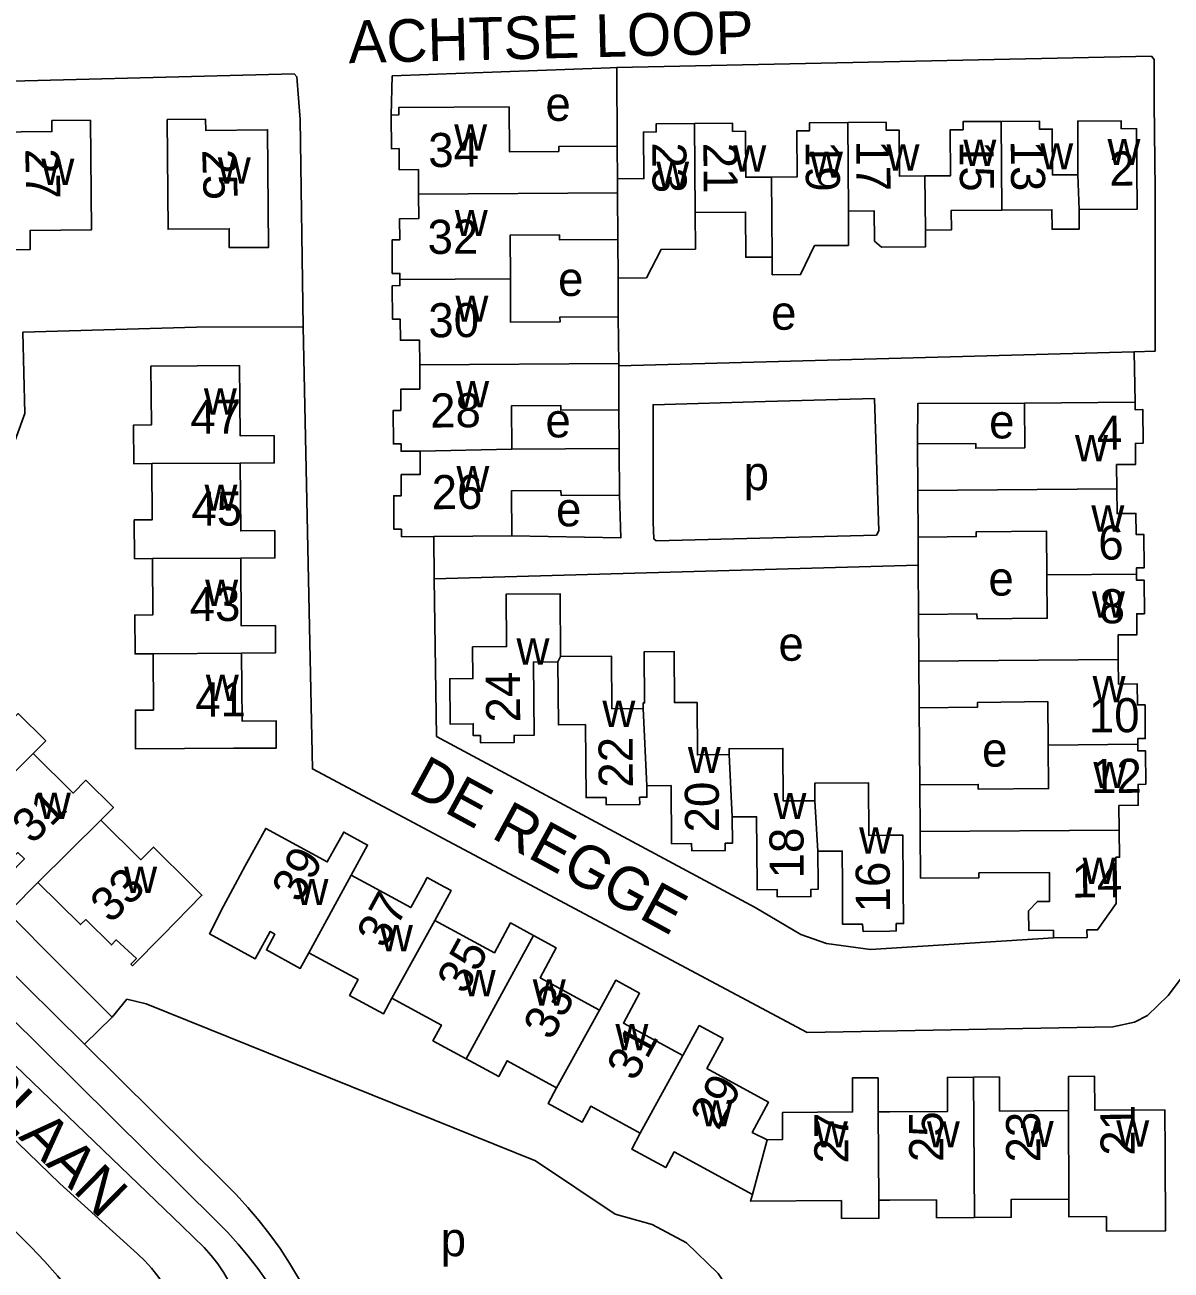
# Model space of a CAD drawing. Extents: x 156721 to 158827, y 386657 to 388950.
# Drawn here: x 157898.5 to 158033, y 387454.8 to 387600.8 of the extents above; entities that cross this region are included whole.
import ezdxf

# ---------------------------------------------------------------- set-up
doc = ezdxf.new("R2010")
doc.units = 0
for name, color, linetype in [('BLT_Basislijn', 7, 'Continuous'), ('BLT_Bebouwing', 7, 'Continuous'), ('BLT_Centroide', 7, 'Continuous'), ('BLT_Huisnummer', 7, 'Continuous'), ('BLT_Huisnummer_ tussenligend', 7, 'Continuous'), ('BLT_Onderverdeling_panden', 7, 'Continuous'), ('BLT_Straatnaam', 7, 'Continuous')]:
    doc.layers.add(name, color=color, linetype=linetype)

msp = doc.modelspace()

# ---------------------------------------------------------------- linework, layer by layer
at = {"layer": 'BLT_Basislijn'}
for p, q in [((157968.01, 387586.61), (157967.99, 387595.81)), ((157968.12, 387571.13), (157968.15, 387566.6)), ((157968.19, 387560.85), (158028.67, 387562.48)), ((158028.67, 387562.48), (158028.8, 387556.58)), ((157968.22, 387555.68), (157968.25, 387551.13)), ((157946.55, 387535.85), (157946.51, 387540.82)), ((158003.32, 387540.75), (158003.34, 387537.44)), ((157905.51, 387481.25), (157848.93, 387537.22)), ((158003.34, 387537.44), (158003.39, 387531.68)), ((158003.54, 387511.67), (158003.47, 387520.73)), ((157846.26, 387519.37), (157902.62, 387464.91)), ((157921.86, 387465.08), (157905.51, 387481.25)), ((157902.62, 387464.91), (157911.72, 387456.67)), ((157919.56, 387457.42), (157916.95, 387459.93))]:
    msp.add_line(p, q, dxfattribs=at)
for points in [[(157967.99, 387595.81), (158030.71, 387597.15), (158031.03, 387596.78), (158031.04, 387591.6), (158031.16, 387581.55), (158031.13, 387562.54), (158028.67, 387562.48)], [(157941.5, 387590.24), (157941.63, 387594.85), (157967.19, 387595.79), (157967.99, 387595.81)], [(157867.9, 387593.86), (157879.95, 387594.35), (157887.95, 387594.01), (157930.12, 387595.07), (157930.44, 387594.75), (157930.8, 387589.72), (157931.18, 387565.39)], [(157931.18, 387565.39), (157918.65, 387565.36), (157898.28, 387564.78), (157898.5, 387555.26), (157894.88, 387545.33), (157882.58, 387532.55), (157875.52, 387525.38), (157871.76, 387521.45)], [(158050, 387530.58), (158045.98, 387530.47), (158041.99, 387530.39), (158042.21, 387499.63), (158032.66, 387486.97), (158030.23, 387484.62), (158028.73, 387483.83), (158026.16, 387483.3), (157990.32, 387482.65), (157932.26, 387513.56), (157931.18, 387565.39)], [(157985.42, 387556.64), (157998.2, 387556.99), (157998.71, 387541.47), (157998.43, 387540.99), (157972.59, 387540.29), (157972.32, 387540.53), (157972.24, 387542.48), (157972.22, 387556.27), (157985.42, 387556.64)], [(158015.81, 387556.47), (158003.3, 387556.43), (158003.24, 387551.69)], [(157955.65, 387540.89), (157968.46, 387540.67), (157968.29, 387545.67)], [(158003.34, 387537.44), (157946.55, 387535.85)], [(157946.55, 387535.85), (157946.82, 387517.36), (157984.19, 387497.31), (157989.55, 387494.14), (157992.58, 387493.09), (157997.76, 387492.37), (158019.21, 387493.73)], [(157921.02, 387460.48), (157855.63, 387525.18), (157851.43, 387523.47)], [(157916.95, 387459.93), (157891.13, 387484.75), (157851.43, 387523.47)], [(157908.77, 387484.42), (157871.76, 387521.45)], [(157992.06, 387443.43), (157983.32, 387449.11), (157979.87, 387454.37), (157976.14, 387457.96), (157972.11, 387460.13), (157967.78, 387461.33), (157958.43, 387467.56), (157912.75, 387485.99), (157910.48, 387486.54), (157908.77, 387484.42)], [(157905.51, 387481.25), (157908.77, 387484.42)], [(157921.86, 387465.08), (157923.3, 387463.62), (157924.68, 387462.12), (157926, 387460.55), (157927.25, 387458.94), (157928.45, 387457.28), (157929.57, 387455.58), (157930.63, 387453.83), (157931.62, 387452.04), (157932.54, 387450.22), (157933.39, 387448.36), (157934.17, 387446.47), (157934.87, 387444.55), (157935.49, 387442.6), (157936.04, 387440.63), (157936.18, 387440.04)], [(157894.22, 387462.09), (157895.95, 387460.61), (157897.64, 387459.06), (157899.26, 387457.46), (157900.83, 387455.8), (157902.34, 387454.09), (157903.79, 387452.33), (157905.18, 387450.51), (157906.5, 387448.65), (157907.76, 387446.75), (157908.95, 387444.8), (157910.07, 387442.81), (157911.12, 387440.78), (157912.1, 387438.71)], [(157921.02, 387460.48), (157922.32, 387459.18), (157923.55, 387457.82), (157924.73, 387456.41), (157925.84, 387454.96), (157926.89, 387453.45), (157927.87, 387451.91), (157928.78, 387450.32), (157929.63, 387448.69), (157930.4, 387447.02), (157931.1, 387445.33), (157931.72, 387443.6), (157932.27, 387441.85), (157932.74, 387440.08), (157933.13, 387438.29), (157933.44, 387436.49), (157933.51, 387436.03)], [(157919.56, 387457.42), (157920.39, 387456.48), (157921.16, 387455.48), (157921.87, 387454.44), (157922.5, 387453.36), (157923.07, 387452.23), (157923.56, 387451.08), (157923.98, 387449.89), (157924.33, 387448.68), (157924.59, 387447.45), (157924.78, 387446.21), (157924.87, 387445.26)], [(157911.72, 387456.67), (157912.58, 387455.85), (157913.38, 387454.97), (157914.13, 387454.05), (157914.81, 387453.07), (157915.42, 387452.05), (157915.97, 387451), (157916.44, 387449.9), (157916.83, 387448.78), (157917.15, 387447.64), (157917.4, 387446.48), (157917.56, 387445.3), (157917.64, 387444.25)]]:
    msp.add_lwpolyline(points, dxfattribs=at)
at = {"layer": 'BLT_Bebouwing'}
for p, q in [((157968.01, 387586.61), (157968.04, 387582.77)), ((157968.15, 387566.6), (157968.19, 387561.11)), ((157968.19, 387561.11), (157968.19, 387560.85)), ((157968.19, 387560.85), (157968.22, 387555.68)), ((158015.81, 387556.47), (158028.8, 387556.58)), ((157955.65, 387551.05), (157968.25, 387551.13)), ((157968.25, 387551.13), (157968.29, 387545.67)), ((158003.28, 387546.22), (158003.24, 387551.69)), ((158003.32, 387540.75), (158003.28, 387546.22)), ((158003.43, 387526.21), (158003.39, 387531.68)), ((158003.47, 387520.73), (158003.43, 387526.21)), ((158003.58, 387506.2), (158003.54, 387511.67))]:
    msp.add_line(p, q, dxfattribs=at)
for points in [[(157968.01, 387586.61), (157961.16, 387586.56), (157961.16, 387585.99), (157955.36, 387585.95), (157955.33, 387591.2), (157942.38, 387591.13), (157942.39, 387590.26), (157941.5, 387590.24)], [(157941.5, 387590.24), (157941.53, 387586.3), (157942.42, 387586.31), (157942.44, 387583.84), (157944.69, 387583.86), (157944.71, 387580.98)], [(157977.07, 387589.25), (157972.59, 387589.22), (157972.6, 387588.27), (157971.09, 387588.25), (157971.15, 387582.8), (157968.04, 387582.77)], [(157986.12, 387582.97), (157983.11, 387582.95), (157983.08, 387588.35), (157981.56, 387588.34), (157981.56, 387589.28), (157977.07, 387589.25)], [(157995.08, 387589.38), (157990.59, 387589.34), (157990.6, 387588.4), (157989.09, 387588.39), (157989.12, 387582.99), (157986.12, 387582.97)], [(158004.13, 387583.11), (158001.13, 387583.09), (158001.09, 387588.48), (158000, 387588.47), (157999.58, 387588.47), (157999.57, 387589.41), (157995.08, 387589.38)], [(158004.13, 387583.11), (158007.13, 387583.13), (158007.1, 387588.52), (158008.61, 387588.53), (158008.6, 387589.48), (158013.08, 387589.51)], [(158013.08, 387589.51), (158017.56, 387589.54), (158017.57, 387588.6), (158019.07, 387588.6), (158019.08, 387583.23), (158022.08, 387583.23)], [(158022.08, 387583.23), (158022.07, 387589.54), (158027.15, 387589.59), (158027.15, 387588.66), (158028.96, 387588.65), (158029.02, 387579.21), (158022.21, 387579.16)], [(157944.71, 387580.98), (157944.73, 387578.11), (157942.48, 387578.09), (157942.5, 387575.61), (157941.6, 387575.6), (157941.62, 387571.67), (157942.52, 387571.67), (157942.53, 387570.96)], [(157968.12, 387571.13), (157971.45, 387571.16), (157973.16, 387574.49), (157977.2, 387574.53), (157977.16, 387578.83)], [(157977.16, 387578.83), (157983.08, 387578.87), (157983.11, 387573.57), (157986.2, 387573.59)], [(157986.2, 387573.59), (157986.22, 387571.51), (157989.53, 387571.53), (157991.18, 387574.93), (157995.14, 387574.96), (157995.16, 387578.98)], [(157995.16, 387578.98), (157998.19, 387579), (157998.22, 387575.47), (157999.05, 387574.74), (158004.19, 387574.78), (158004.18, 387576.75)], [(158013.15, 387579.11), (158007.21, 387579.07), (158007.23, 387576.77), (158004.18, 387576.75)], [(158022.21, 387579.16), (158022.23, 387576.87), (158019.04, 387576.85), (158019.02, 387579.15), (158013.15, 387579.11)], [(157968.09, 387575.67), (157961.24, 387575.62), (157961.24, 387576.19), (157955.44, 387576.15), (157955.48, 387571.05)], [(157968.09, 387575.67), (157968.12, 387571.13)], [(157942.53, 387570.96), (157942.53, 387570.24), (157941.63, 387570.23), (157941.66, 387566.3), (157942.56, 387566.3), (157942.57, 387563.83), (157944.82, 387563.84), (157944.84, 387560.97)], [(157955.48, 387571.05), (157955.51, 387565.94), (157961.31, 387565.98), (157961.3, 387566.55), (157968.15, 387566.6)], [(157913.39, 387549.36), (157911.29, 387549.34), (157911.26, 387553.89), (157913.36, 387553.9), (157913.3, 387560.81), (157918.71, 387560.84), (157923.71, 387560.87), (157923.76, 387552.63), (157927.76, 387552.65), (157927.77, 387549.45), (157923.78, 387549.42)], [(157944.84, 387560.97), (157944.85, 387558.1), (157942.61, 387558.09), (157942.62, 387555.6), (157941.73, 387555.6), (157941.75, 387551.67), (157942.65, 387551.68), (157942.65, 387550.81), (157944.9, 387550.82)], [(157968.22, 387555.68), (157961.4, 387555.62), (157961.39, 387556.19), (157955.61, 387556.14), (157955.65, 387551.05)], [(158003.24, 387551.69), (158010.09, 387551.74), (158010.09, 387551.17), (158015.85, 387551.22), (158015.81, 387556.47)], [(158028.8, 387556.58), (158028.8, 387555.69), (158029.7, 387555.7), (158029.73, 387551.75), (158028.83, 387551.74), (158028.85, 387549.27), (158026.62, 387549.25), (158026.64, 387546.39)], [(157944.9, 387550.82), (157944.91, 387548.09), (157942.67, 387548.08), (157942.68, 387545.6), (157941.79, 387545.6), (157941.82, 387541.66), (157942.7, 387541.67), (157942.72, 387540.79), (157946.51, 387540.82)], [(157913.47, 387538.22), (157911.38, 387538.21), (157911.34, 387542.75), (157913.44, 387542.76), (157913.39, 387549.36)], [(157923.78, 387549.42), (157923.84, 387541.47), (157927.84, 387541.5), (157927.86, 387538.31), (157923.85, 387538.28)], [(157955.65, 387540.89), (157955.61, 387546.16), (157961.42, 387546.2), (157961.43, 387545.63), (157968.29, 387545.67)], [(158026.64, 387546.39), (158026.67, 387543.51), (158028.89, 387543.53), (158028.91, 387541.05), (158029.81, 387541.06), (158029.84, 387537.13), (158028.94, 387537.12), (158028.95, 387536.41)], [(157946.51, 387540.82), (157955.65, 387540.89)], [(158018.45, 387536.33), (158018.41, 387541.43), (158010.16, 387541.37), (158010.16, 387540.8), (158003.32, 387540.75)], [(157913.55, 387527.06), (157911.44, 387527.05), (157911.41, 387531.6), (157913.51, 387531.61), (157913.47, 387538.22)], [(157923.85, 387538.28), (157923.91, 387530.33), (157927.91, 387530.36), (157927.92, 387527.16), (157923.92, 387527.13)], [(158003.39, 387531.68), (158010.23, 387531.73), (158010.24, 387531.16), (158018.49, 387531.23), (158018.45, 387536.33)], [(158028.95, 387536.41), (158028.95, 387535.7), (158029.85, 387535.7), (158029.88, 387531.76), (158028.98, 387531.75), (158029, 387529.28), (158026.79, 387529.26), (158026.81, 387526.38)], [(157961.37, 387526.72), (157961.31, 387534.09), (157955, 387534.05), (157955.04, 387527.9), (157951.05, 387527.87), (157951.08, 387524.14), (157948.37, 387524.12), (157948.41, 387518.82), (157951.12, 387518.84), (157951.13, 387517.46), (157951.97, 387517.46), (157951.98, 387516.61), (157955.92, 387516.64), (157955.91, 387517.49), (157958.27, 387517.51), (157958.19, 387526.08), (157961.05, 387526.11)], [(157923.92, 387527.13), (157923.99, 387519.17), (157927.99, 387519.2), (157928.01, 387516), (157923.01, 387515.97), (157911.51, 387515.9), (157911.49, 387520.45), (157913.59, 387520.46), (157913.55, 387527.06)], [(157981.14, 387515.23), (157977.44, 387515.2), (157977.4, 387521.35), (157974.74, 387521.33), (157974.69, 387527.33), (157971.19, 387527.3), (157971.24, 387521.3), (157971.08, 387521.3), (157971.08, 387520.63)], [(157961.05, 387526.11), (157961.12, 387518.72), (157964.29, 387518.75), (157964.36, 387510.18), (157966.71, 387510.19), (157966.72, 387509.34), (157970.66, 387509.38), (157970.65, 387510.23), (157971.5, 387510.23), (157971.49, 387511.55)], [(157971.08, 387520.63), (157967.4, 387520.61), (157967.36, 387526.77), (157961.37, 387526.72)], [(158026.81, 387526.38), (158026.83, 387523.5), (158029.05, 387523.52), (158029.07, 387521.06), (158029.96, 387521.06), (158029.99, 387517.11), (158029.1, 387517.11), (158029.11, 387516.45)], [(157891.56, 387523.19), (157896.25, 387518.55), (157897.73, 387520.04), (157900.96, 387516.84), (157899.5, 387515.36)], [(158018.59, 387516.35), (158018.54, 387521.45), (158010.3, 387521.36), (158010.31, 387520.8), (158003.47, 387520.73)], [(157899.5, 387515.36), (157904.19, 387510.72), (157905.66, 387512.22), (157908.9, 387509.02), (157907.42, 387507.53)], [(157991.2, 387509.82), (157987.5, 387509.8), (157987.46, 387515.96), (157981.14, 387515.91), (157981.14, 387515.23)], [(158003.54, 387511.67), (158010.38, 387511.74), (158010.39, 387511.17), (158018.64, 387511.25), (158018.59, 387516.35)], [(158029.11, 387516.45), (158029.11, 387515.68), (158030.01, 387515.69), (158030.04, 387511.75), (158029.14, 387511.74), (158029.16, 387509.28), (158026.89, 387509.25), (158026.93, 387506.37)], [(157971.49, 387511.55), (157974.34, 387511.59), (157974.4, 387504.78), (157976.75, 387504.8), (157976.76, 387503.95), (157980.7, 387503.98), (157980.69, 387504.83), (157981.54, 387504.84), (157981.51, 387507.92)], [(157991.57, 387503.91), (157994.43, 387503.92), (157994.45, 387500), (157994.47, 387495.34), (157996.82, 387495.33), (157996.88, 387494.48), (158000, 387494.53), (158000.77, 387494.54), (158000.76, 387495.4), (158001.62, 387495.4), (158001.59, 387500), (158001.55, 387505.78), (158000, 387505.77), (157997.53, 387505.75), (157997.49, 387511.92), (157991.19, 387511.87), (157991.2, 387509.82)], [(157892.11, 387508.07), (157897.1, 387503.12), (157897.7, 387503.73), (157898.45, 387502.99), (157894.65, 387499.13), (157896.89, 387497.06), (157900.03, 387500.24)], [(157981.51, 387507.92), (157984.37, 387507.95), (157984.43, 387500), (157984.44, 387499.36), (157986.8, 387499.39), (157986.8, 387498.54), (157990.74, 387498.58), (157990.74, 387499.42), (157991.59, 387499.44), (157991.59, 387500), (157991.57, 387503.91)], [(157900.03, 387500.24), (157905.05, 387495.29), (157905.65, 387495.88), (157908.68, 387492.9), (157909.22, 387493.49), (157911.6, 387491.3), (157910.96, 387490.64), (157911.15, 387490.46), (157914.66, 387494.02), (157919.29, 387498.74), (157918.02, 387500), (157913.59, 387504.38), (157912.11, 387502.89), (157907.42, 387507.53)], [(157936.81, 387501.1), (157938.72, 387504.62), (157935.92, 387506.14), (157934, 387502.65), (157926.77, 387506.58), (157924.38, 387502.19), (157923.18, 387500), (157921.8, 387497.47), (157920.16, 387494.21), (157925.53, 387491.27), (157927.29, 387494.47), (157927.85, 387494.16), (157926.85, 387492.32), (157930.82, 387490.15), (157931.83, 387491.99)], [(158019.21, 387493.73), (158019.2, 387494.63), (158016.31, 387494.61), (158016.3, 387496.89), (158017.32, 387498), (158018.75, 387498.01), (158018.74, 387500), (158018.73, 387501.41), (158010.46, 387501.35), (158010.47, 387500.78), (158003.62, 387500.72), (158003.58, 387506.2)], [(158026.93, 387506.37), (158026.96, 387503.18), (158026.53, 387503.18), (158026.56, 387500), (158026.57, 387497.76), (158024.38, 387494.67), (158023.14, 387494.66), (158023.15, 387493.76), (158019.21, 387493.73)], [(157936.81, 387501.1), (157938.83, 387500), (157943.8, 387497.29), (157945.28, 387500), (157945.72, 387500.81), (157947.21, 387500), (157948.52, 387499.29), (157946.61, 387495.78)], [(157946.61, 387495.78), (157953.6, 387491.97), (157955.51, 387495.49), (157958.19, 387494.02)], [(157958.19, 387494.02), (157960.87, 387492.56), (157958.96, 387489.05), (157965.93, 387485.26)], [(157941.59, 387486.67), (157940.59, 387484.82), (157936.61, 387486.99), (157937.62, 387488.83), (157931.83, 387491.99)], [(157965.93, 387485.26), (157967.84, 387488.77), (157970.65, 387487.24), (157968.74, 387483.73), (157975.73, 387479.92)], [(157950.29, 387479.54), (157946.39, 387481.67), (157947.39, 387483.51), (157941.59, 387486.67)], [(157975.73, 387479.92), (157977.64, 387483.44), (157980.45, 387481.92), (157978.54, 387478.41), (157985.78, 387474.45), (157983.86, 387470.92), (157985.6, 387470.05)], [(157960.91, 387476.16), (157955.11, 387479.31), (157954.11, 387477.47), (157950.29, 387479.54)], [(157985.6, 387470.05), (157987.41, 387470.08), (157987.4, 387473.23), (157995.64, 387473.32), (157995.61, 387477.3), (157998.64, 387477.31), (157998.66, 387473.31)], [(157998.66, 387473.31), (158000, 387473.32), (158006.79, 387473.37), (158006.76, 387477.37), (158009.81, 387477.4)], [(158009.81, 387477.4), (158012.86, 387477.43), (158012.89, 387473.41), (158020.99, 387473.47)], [(158020.99, 387473.47), (158020.98, 387477.49), (158024.02, 387477.52), (158024.05, 387473.52), (158032.29, 387473.56), (158032.3, 387468.56), (158032.36, 387459.37), (158025.44, 387459.32), (158025.43, 387461.03), (158021.03, 387461), (158021.03, 387463.1)], [(157970.73, 387470.81), (157964.92, 387473.98), (157963.91, 387472.13), (157959.91, 387474.31), (157960.91, 387476.16)], [(157983.91, 387463.61), (157980.79, 387465.31), (157974.72, 387468.63), (157973.71, 387466.78), (157969.72, 387468.96), (157970.73, 387470.81)], [(157998.71, 387462.95), (157998.72, 387460.85), (157994.35, 387460.82), (157994.33, 387462.92), (157983.66, 387462.83), (157983.91, 387463.61)], [(158009.95, 387460.93), (158005.49, 387460.9), (158005.48, 387462.99), (158000, 387462.96), (157998.71, 387462.95)], [(158021.03, 387463.1), (158014.25, 387463.05), (158014.26, 387460.96), (158009.95, 387460.93)]]:
    msp.add_lwpolyline(points, dxfattribs=at)
for points in [[(157915.22, 387589.74), (157919.7, 387589.77), (157919.74, 387588.45), (157927, 387588.53), (157927.1, 387574.73), (157922.5, 387574.7), (157922.49, 387576.92), (157915.32, 387576.86)], [(157906.2, 387589.65), (157906.31, 387576.77), (157899.12, 387576.71), (157899.14, 387574.49), (157894.54, 387574.45), (157894.43, 387588.25), (157901.68, 387588.31), (157901.69, 387589.61)]]:
    msp.add_lwpolyline(points, close=True, dxfattribs=at)
at = {"layer": 'BLT_Onderverdeling_panden'}
for p, q in [((157977.07, 387589.25), (157977.16, 387578.83)), ((157995.08, 387589.38), (157995.16, 387578.98)), ((158013.08, 387589.51), (158013.15, 387579.11)), ((157968.04, 387582.77), (157968.05, 387581.14)), ((157986.12, 387582.97), (157986.2, 387573.59)), ((158004.13, 387583.11), (158004.18, 387576.75)), ((158022.08, 387583.23), (158022.21, 387579.16)), ((157944.71, 387580.98), (157968.05, 387581.14)), ((157968.05, 387581.14), (157968.09, 387575.67)), ((157955.48, 387571.05), (157942.53, 387570.96)), ((157944.84, 387560.97), (157968.19, 387561.11)), ((157955.65, 387551.05), (157944.9, 387550.82)), ((157913.39, 387549.36), (157923.78, 387549.42)), ((158003.28, 387546.22), (158026.64, 387546.39)), ((157913.47, 387538.22), (157923.85, 387538.28)), ((158018.45, 387536.33), (158028.95, 387536.41)), ((157913.55, 387527.06), (157923.92, 387527.13)), ((157961.37, 387526.72), (157961.05, 387526.11)), ((158003.43, 387526.21), (158026.81, 387526.38)), ((157971.08, 387520.63), (157971.49, 387511.55)), ((157899.5, 387515.36), (157892.11, 387508.07)), ((158018.59, 387516.35), (158029.11, 387516.45)), ((157981.14, 387515.23), (157981.51, 387507.92)), ((157991.2, 387509.82), (157991.57, 387503.91)), ((157907.42, 387507.53), (157900.03, 387500.24)), ((158003.58, 387506.2), (158026.93, 387506.37)), ((157936.81, 387501.1), (157931.83, 387491.99)), ((157946.61, 387495.78), (157941.59, 387486.67)), ((157958.19, 387494.02), (157950.29, 387479.54)), ((157965.93, 387485.26), (157960.91, 387476.16)), ((157975.73, 387479.92), (157970.73, 387470.81)), ((158009.81, 387477.4), (158009.95, 387460.93)), ((157998.66, 387473.31), (157998.71, 387462.95)), ((158020.99, 387473.47), (158021.03, 387463.1)), ((157985.6, 387470.05), (157983.91, 387463.61))]:
    msp.add_line(p, q, dxfattribs=at)

# ---------------------------------------------------------------- texts
at = {"layer": 'BLT_Centroide'}
for s, p in [('e', (157959.6, 387589.57)), ('w', (157948.89, 387586.09)), ('w', (158008.64, 387584.28)), ('w', (158017.66, 387583.88)), ('w', (158025.55, 387584.38)), ('w', (157981.64, 387583.61)), ('w', (157990.64, 387582.89)), ('w', (157999.62, 387583.73)), ('w', (157900.45, 387582.06)), ('w', (157921.15, 387582.22)), ('w', (157972.59, 387581.7)), ('w', (157948.97, 387576.06)), ('e', (157961.08, 387569.03)), ('w', (157949.04, 387566)), ('e', (157986.08, 387565.07)), ('w', (157919.52, 387555.12)), ('w', (157949.12, 387555.97)), ('e', (157959.6, 387552.44)), ('e', (158011.66, 387552.32)), ('w', (158021.74, 387549.64)), ('w', (157949.15, 387546.03)), ('p', (157982.86, 387546.25)), ('w', (157919.59, 387543.83)), ('e', (157960.84, 387542.01)), ('w', (158023.66, 387541.38)), ('w', (157919.67, 387532.67)), ('e', (158011.58, 387533.88)), ('w', (158023.73, 387531.31)), ('w', (157956.2, 387525.78)), ('e', (157986.94, 387526.24)), ('w', (157919.75, 387521.52)), ('w', (158023.8, 387521.38)), ('w', (157966.28, 387518.47)), ('e', (158010.83, 387513.82)), ('w', (157976.31, 387513.06)), ('w', (158023.89, 387511.31)), ('w', (157900.04, 387507.69)), ('w', (157986.36, 387507.66)), ('w', (157996.41, 387503.62)), ('w', (158022.64, 387500.06)), ('w', (157910.16, 387499)), ('w', (157930.27, 387497.58)), ('w', (157940.17, 387492.16)), ('w', (157949.89, 387486.88)), ('w', (157958.11, 387485.78)), ('w', (157967.81, 387480.56)), ('w', (157977.71, 387471.62)), ('w', (157991.22, 387469.16)), ('w', (158004.36, 387469.16)), ('w', (158015.37, 387469.19)), ('w', (158026.58, 387469.25)), ('p', (157947.31, 387456.39))]:
    msp.add_text(s, height=4, dxfattribs=at).set_placement(p)
at = {"layer": 'BLT_Huisnummer'}
for s, rotation, p in [('34', 0.4521, (157945.86, 387584.14)), ('17', 270.3859, (157996.06, 387587.26)), ('13', 270.3859, (158014.2, 387587.25)), ('27', 271.5526, (157898.54, 387586.28)), ('25', 271.8639, (157919.31, 387586.19)), ('23', 270.3859, (157972.13, 387587.03)), ('2', 0.3957, (158025.78, 387581.97)), ('30', 0.4521, (157945.87, 387564.17)), ('47', 0.3736, (157917.94, 387552.85)), ('4', 0.4291, (158024.33, 387550.99)), ('26', 0.4521, (157946.27, 387544.01)), ('6', 0.4291, (158024.48, 387538.09)), ('24', 90.4878, (157956.64, 387519.01)), ('41', 0.3736, (157918.51, 387519.68)), ('10', 0.4291, (158023.38, 387517.82)), ('20', 90.3862, (157979.98, 387506.12)), ('39', 61.3794, (157930.78, 387497.7)), ('16', 90.3862, (158000.03, 387496.73)), ('14', 0.4291, (158021.36, 387498.46)), ('33', 43.6229, (157908.56, 387495.32)), ('33', 61.3794, (157960.3, 387481.57)), ('29', 61.3794, (157979.89, 387471.03)), ('27', 90.1595, (157995.15, 387467.27)), ('21', 90.1595, (158028.74, 387468.19))]:
    msp.add_text(s, height=4, rotation=rotation, dxfattribs=at).set_placement(p)
at = {"layer": 'BLT_Huisnummer_ tussenligend'}
for s, rotation, p in [('21', 270.3859, (157978.13, 387586.99)), ('19', 270.3859, (157990.12, 387587.2)), ('15', 270.3859, (158008.2, 387587.2)), ('32', 0.4521, (157945.78, 387573.95)), ('28', 0.4521, (157946.08, 387553.59)), ('45', 0.3736, (157918.06, 387542.06)), ('43', 0.3736, (157917.86, 387530.87)), ('8', 0.4291, (158024.64, 387530.62)), ('22', 90.3862, (157969.86, 387511.37)), ('12', 0.4291, (158023.64, 387510.71)), ('31', 43.6229, (157899.37, 387504.61)), ('18', 90.3862, (157989.91, 387500.72)), ('37', 61.3794, (157940.75, 387492.35)), ('35', 61.3794, (157950.18, 387486.97)), ('31', 61.3794, (157970.09, 387476.77)), ('25', 90.1595, (158006.28, 387467.44)), ('23', 90.1595, (158017.66, 387467.39))]:
    msp.add_text(s, height=4, rotation=rotation, dxfattribs=at).set_placement(p)
at = {"layer": 'BLT_Straatnaam'}
for s, rotation, p in [('ACHTSE LOOP', 1.398, (157936.53, 387596.33)), ('DE REGGE', 331.4393, (157943.32, 387510.87)), ('COR GEHRELSLAAN', 315.2687, (157860.47, 387507.18))]:
    msp.add_text(s, height=5, rotation=rotation, dxfattribs=at).set_placement(p)

doc.saveas('drawing.dxf')
